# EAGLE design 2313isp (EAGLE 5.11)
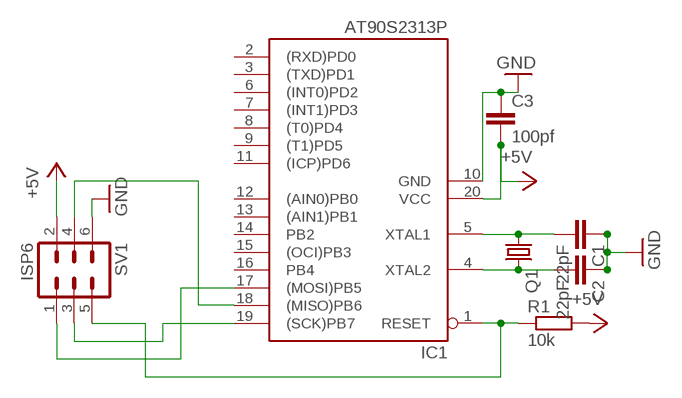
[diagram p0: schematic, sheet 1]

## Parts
C1  22pF  C-EU025-024X044  [C025-024X044]
C2  22pF  C-EU025-024X044  [C025-024X044]
C3  100pf  C-EU025-024X044  [C025-024X044]
IC1  AT90S2313P  [DIL20]
Q1  CRYSTALHC49U-V  [HC49U-V]
R1  10k  R-EU_0204/2V  [0204V]
SV1  ISP6  ML6  [ML6]

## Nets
+5V: C3.2 IC1.20(VCC) R1.2 SV1.2
GND: C1.1 C2.1 C3.1 IC1.10(GND) SV1.6
N$1: C1.2 IC1.5(XTAL1) Q1.1
N$2: C2.2 IC1.4(XTAL2) Q1.2
N$4: IC1.17((MOSI)PB5) SV1.1
N$5: IC1.19((SCK)PB7) SV1.3
N$6: IC1.1(RESET) R1.1 SV1.5
N$7: IC1.18((MISO)PB6) SV1.4
Unconnected: IC1.2((RXD)PD0) IC1.3((TXD)PD1) IC1.6((INT0)PD2) IC1.7((INT1)PD3) IC1.8((T0)PD4) IC1.9((T1)PD5) IC1.11((ICP)PD6) IC1.12((AIN0)PB0) IC1.13((AIN1)PB1) IC1.14(PB2) IC1.15((OCI)PB3) IC1.16(PB4)

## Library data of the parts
C1-C3 = resistor:C-EU: CAPACITOR, European symbol
IC1 = atmel:AT90S2313: MICROCONTROLLER 2 Kbytes FLASH 128 bytes SRAM 128 bytes EEPROM UART; OC_FARNELL: unknown; OC_NEWARK: unknown
Q1 = crystal:CRYSTAL: CRYSTAL; OC_FARNELL: 1666969; OC_NEWARK: unknown
R1 = resistor:R-EU_: RESISTOR, European symbol
SV1 = con-ml:ML6: HARTING; OC_FARNELL: unknown; OC_NEWARK: unknown

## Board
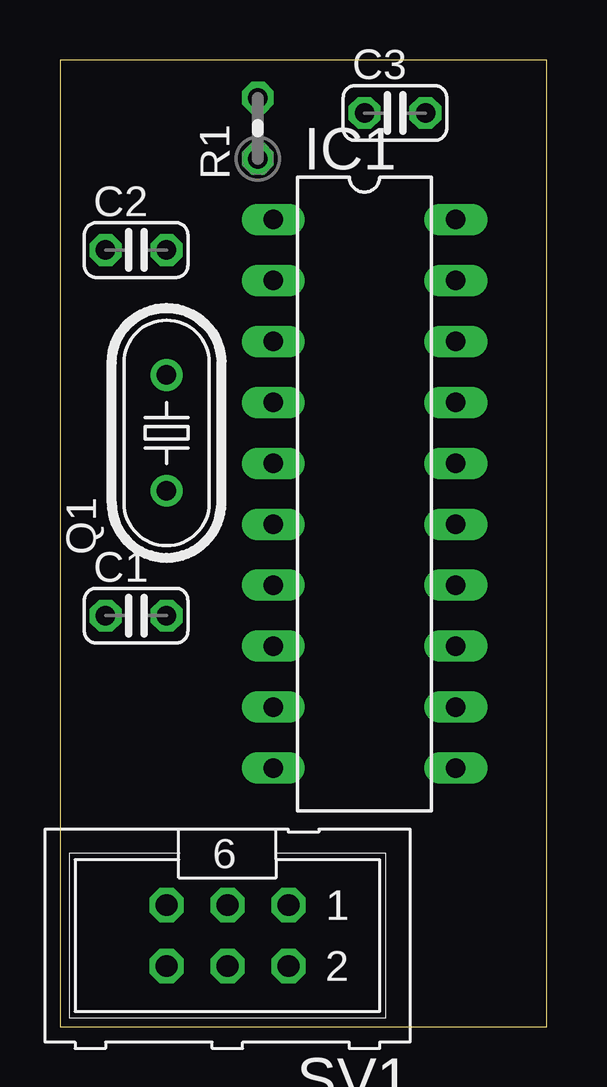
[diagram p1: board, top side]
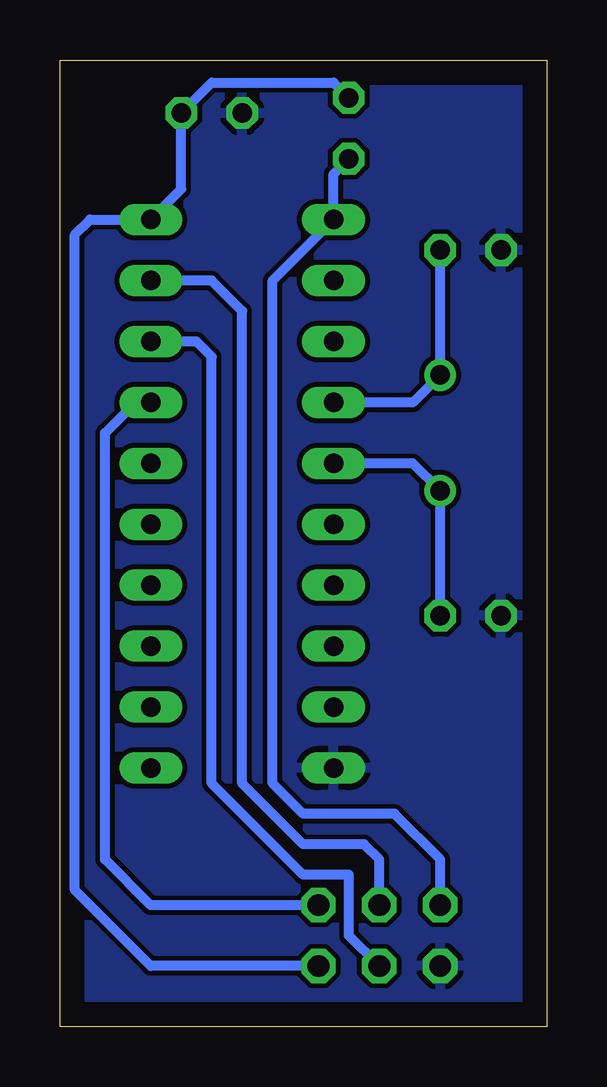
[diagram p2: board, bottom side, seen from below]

Size 20.3 x 40.31 mm. Coordinates in mm from the lower left corner, seen from the top.
Outline: 0,0 20.3,0 20.3,40.31 0,40.31 0,0
Copper layers (1*16): Top 0.035mm / dielectric 1.5mm / Bottom 0.035mm
Design rules "default": minimum track width 10mil, minimum drill 24mil, track to track 8mil, track to pad 8mil, pad to pad 8mil, via to via 8mil, smd to smd 8mil, copper to edge 40mil, drill to drill 8mil, minimum pad ring 10mil, minimum via ring 8mil, stop-mask expansion 4mil, vias tented up to drill 0mil, thermal gap 10mil

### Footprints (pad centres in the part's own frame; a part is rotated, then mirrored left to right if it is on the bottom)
C025-024X044 = drill 0.813 octagon: 1 -1.27,0; 2 1.27,0
DIL20 = drill 0.813 long: 1 -11.43,-3.81; 2 -8.89,-3.81; 3 -6.35,-3.81; 4 -3.81,-3.81; 5 -1.27,-3.81; 6 1.27,-3.81; 7 3.81,-3.81; 8 6.35,-3.81; 9 8.89,-3.81; 10 11.43,-3.81; 11 11.43,3.81; 12 8.89,3.81; 13 6.35,3.81; 14 3.81,3.81; 15 1.27,3.81; 16 -1.27,3.81; 17 -3.81,3.81; 18 -6.35,3.81; 19 -8.89,3.81; 20 -11.43,3.81
HC49U-V = drill 0.813 round: 1 -2.413,0; 2 2.413,0
0204V = drill 0.813 octagon: 1 -1.27,0; 2 1.27,0
ML6 = drill 0.914 octagon: 1 -2.54,-1.27; 2 -2.54,1.27; 3 0,-1.27; 4 0,1.27; 5 2.54,-1.27; 6 2.54,1.27

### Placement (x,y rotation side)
C1  3.17,17.14 0 top
C2  3.17,32.38 0 top
C3  13.97,38.1 0 top
IC1  12.7,22.23 270 top
Q1  4.45,24.77 90 top
R1  8.26,37.47 90 top
SV1  6.99,3.81 180 top

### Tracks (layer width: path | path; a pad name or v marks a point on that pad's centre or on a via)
+5V
  Bottom 0.406: R1.2 8.89,39.37 13.97,39.37 C3.2 15.24,34.92 IC1.20 19.05,33.66 19.68,33.02 19.68,5.71 16.51,2.54 SV1.2
GND
  pour Bottom: -2.54,40.64 -2.54,-1.27 20.32,-1.27 20.32,40.64
N$1
  Bottom 0.406: IC1.5 5.59,23.5 Q1.1 C1.2
N$2
  Bottom 0.406: IC1.4 5.59,26.04 Q1.2 C2.2
N$4
  Bottom 0.406: IC1.17 17.14,26.04 18.41,24.77 18.41,6.99 16.51,5.08 SV1.1
N$5
  Bottom 0.406: IC1.19 13.97,31.11 12.7,29.84 12.7,10.16 10.16,7.62 7.62,7.62 6.99,6.99 SV1.3
N$6
  Bottom 0.406: R1.1 8.89,35.56 IC1.1 11.43,31.11 11.43,10.16 10.16,8.89 6.35,8.89 4.45,6.99 SV1.5
N$7
  Bottom 0.406: IC1.18 14.61,28.57 13.97,27.94 13.97,10.16 10.16,6.35 8.26,6.35 8.26,3.81 SV1.4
